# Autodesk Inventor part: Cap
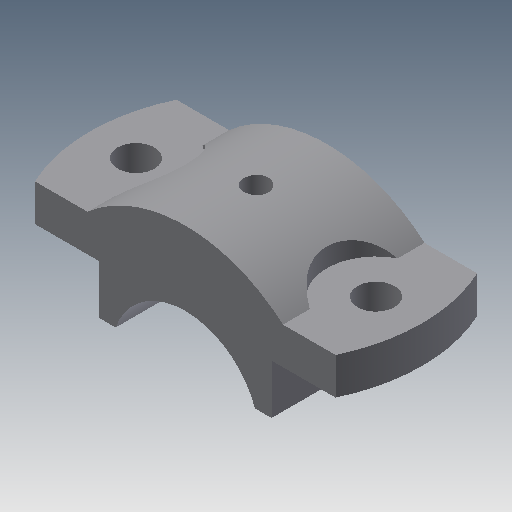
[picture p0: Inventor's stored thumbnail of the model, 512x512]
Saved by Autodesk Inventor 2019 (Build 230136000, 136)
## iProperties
Created: 2009-04
Part Number: Cap
Document SubType Name: Modeling
Designer: Sham
Density: 1 g/cm^3
Material: Generic
Appearance: Default
Author: Sham
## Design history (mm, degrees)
sketch "Sketch1"
  geometry: L1 (-48.857, 23)-(48.857, 23); L2 (48.857, -23)-(-48.857, -23); A1 r 54 centre (0, 0) between (-48.857, 23) and (-48.857, -23); A2 r 54 centre (0, 0) between (48.857, -23) and (48.857, 23); 1 further point
  constraints: 4 end point, 4 point on circle, 2 centre point, 2 coincident, 1 horizontal, 1 parallel, 1 other
  dimensions: "d3" = 54 radius of A1; "d4" = 54 radius of A2; "d5" = 46 distance between parallel lines of L2 L1; "d6" = 23 distance from line of point (0, 0) L1
extrude "Extrusion1" new body sketch "Sketch1" distance "d7" = 12; taper "d8" = 0 deg
sketch "Sketch3"
  geometry: L1 (20.906, 0)-(20.906, -16); L2 (76.906, -0.137)-(76.906, -16.137); L3 (20.906, -16)-(26.23, -16); L4 (71.532, -16.137)-(76.906, -16.137); L5 (76.906, -0.137)-(76.857, 12); L6 (97.714, 0)-(0, 0) reference; L7 (76.857, 12)-(80.606, 12); L8 (17.108, 12)-(20.906, 12); L9 (20.906, 12)-(20.906, 0); L10 (0, 12)-(97.714, 12) reference; A1 r 24 centre (48.857, -24) between (71.532, -16.137) and (26.23, -16); A2 r 48 centre (48.857, -24) between (80.606, 12) and (17.108, 12); 3 further points
  constraints: 16 end point, 4 point on circle, 3 parallel, 3 perpendicular, 2 centre point, 2 coincident, 2 vertical alignment, 1 collinear, 1 midpoint, 1 vertical, 2 other
  dimensions: "d17" = 48 diameter of A1; "d18" = 16 distance of L1.start L1.end; "d19" = 56 distance between parallel lines of L2 L1; "d21" = 8 vertical distance of A1.centre L1.end; "d22" = 48 radius of A2; "d23" = 0 distance from line of L6 L1.start; "d38" = 31.74902 distance of L7.end point (48.857, 12); "d39" = 28 distance from line of point (48.857, 12) L5
extrude "Extrusion2" join sketch "Sketch3" stored distance "d24" = 12; taper "d25" = 0 deg
sketch "Sketch4"
  geometry: 2 further points
  dimensions: "d26" = 78 distance of point (39, 0) point (-39, 0)
hole "Hole1" sketch "Sketch4" at (-39, 0), (39, 0) diameter "d28" = 12; stored, may be unused: countersink angle "d32" = 90 deg, drill point angle "d34" = 118 deg; dims "d29" = 6, "d30" = 4, "d31" = 2, "d33" = 8
sketch "Sketch5"
  geometry: L1 (-31.749, -23)-(-31.749, 23) reference; L2 (-31.749, 14.263)-(-31.749, -14.263); C1 r 6 at (-39, 0) reference; A1 r 16 centre (-39, 0) between (-31.749, -14.263) and (-31.749, 14.263)
  constraints: 2 end point, 2 point on circle, 1 centre point, 1 coincident, 1 collinear, 1 point on line
  dimensions: "d35" = 16 radius of A1
extrude "Extrusion3" cut sketch "Sketch5" distance "d36" = 12; taper "d37" = 0 deg
mirror "Mirror2"
workplane "Work Plane4"
sketch "Sketch6"
  geometry: L1 (-31.749, 0)-(31.749, 0) reference; 1 further point
  dimensions: "d40" = 23 distance from line of L1 point (0, 23)
hole "Hole2" sketch "Sketch6" at (0, 23) diameter "d41" = 6; stored, may be unused: countersink angle "d45" = 90 deg, drill point angle "d47" = 118 deg; dims "d42" = 6, "d43" = 8, "d44" = 16, "d46" = 8
body "Solid1"
